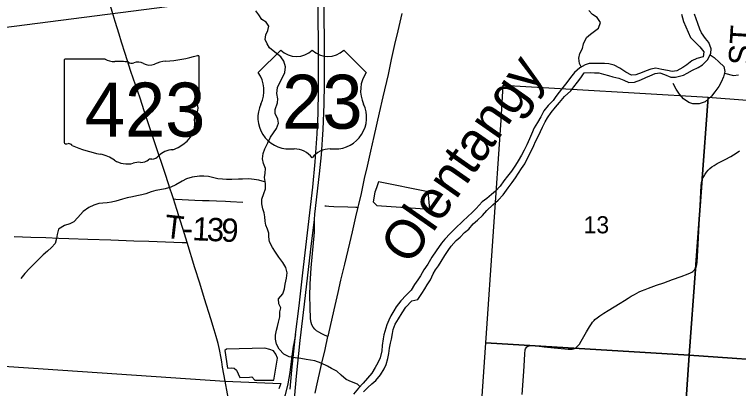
# Model space of a CAD drawing. Extents: x 1584893 to 1934202, y 663575 to 1091909.
# Drawn here: x 1804696 to 1814023, y 898063 to 902888 of the extents above; entities that cross this region are included whole.
import ezdxf

# ---------------------------------------------------------------- set-up
doc = ezdxf.new("R2010")
doc.units = 0
for name, color, linetype in [('GM_X_Corporation', 7, 'Continuous'), ('GM_X_County_Road_Text', 7, 'Continuous'), ('GM_X_Interchange_Ramps', 7, 'Continuous'), ('GM_X_Major_River', 7, 'Continuous'), ('GM_X_Major_River_Text', 7, 'Continuous'), ('GM_X_Minor_Lake', 7, 'Continuous'), ('GM_X_Minor_River', 7, 'Continuous'), ('GM_X_Section', 7, 'Continuous'), ('GM_X_Section_Text', 7, 'Continuous'), ('GM_X_State_Route', 7, 'Continuous'), ('GM_X_State_Shield', 7, 'Continuous'), ('GM_X_Township_Road', 7, 'Continuous'), ('GM_X_Township_Road_Text', 7, 'Continuous'), ('GM_X_US_Location', 7, 'Continuous'), ('GM_X_US_Route', 7, 'Continuous'), ('GM_X_US_Shield', 7, 'Continuous')]:
    doc.layers.add(name, color=color, linetype=linetype)

msp = doc.modelspace()

# ---------------------------------------------------------------- linework, layer by layer
at = {"layer": 'GM_X_Corporation'}
msp.add_lwpolyline([(1803668.3, 898412.1), (1807407.3, 898159.3), (1808126, 898128.1), (1808102.5, 898059.9)], dxfattribs=at)
at = {"layer": 'GM_X_Interchange_Ramps'}
for points in [[(1808734.7, 898733.4), (1808719.4, 898740), (1808689.4, 898753), (1808653.5, 898770.5), (1808616.3, 898790.9), (1808588.6, 898808.9), (1808563.5, 898830.2), (1808542.9, 898855.5), (1808527.9, 898884.2), (1808518.4, 898915.3), (1808511.4, 898964.2), (1808503.2, 899112.3), (1808500.5, 899260.4), (1808504.8, 899408.3), (1808519.4, 899621.7), (1808561.4, 900079.6), (1808560.6, 900147.7), (1808559.4, 900245.2)], [(1808317.9, 898761.3), (1808293.9, 898644.8), (1808285.8, 898604.8), (1808266.6, 898448.2), (1808243.1, 898270.3), (1808217.1, 898125.9), (1808184.2, 897982.8), (1808156.9, 897888.9), (1808123.3, 897797), (1808082.9, 897707.9), (1808016.2, 897577), (1807998.3, 897531.6), (1807990.2, 897500.2), (1807984.8, 897451.6), (1807985, 897386.4), (1807990.2, 897340), (1807991.6, 897328.2)]]:
    msp.add_lwpolyline(points, dxfattribs=at)
at = {"layer": 'GM_X_Major_River'}
for points in [[(1813286.7, 902892.4), (1813315.4, 902797.7), (1813344.4, 902729), (1813373.4, 902658.4), (1813406.5, 902591.7), (1813457.9, 902540.8), (1813525, 902469.7), (1813574.2, 902406.8), (1813567.2, 902342.6), (1813486.7, 902321.7), (1813422.1, 902288.5), (1813357.1, 902237.2), (1813304.5, 902203.8), (1813229.7, 902162.7), (1813169.4, 902153.5), (1813107.4, 902166.4), (1813035.4, 902177.4), (1812959.5, 902196.5), (1812893.1, 902183.4), (1812832.7, 902162.2), (1812782.2, 902138.8), (1812699.5, 902107.8), (1812645.4, 902106.5), (1812571.8, 902145.7), (1812492.3, 902197), (1812422.7, 902236), (1812350.8, 902251.1), (1812298.7, 902253.8), (1812240.6, 902254.6), (1812166.4, 902257.7), (1812100.2, 902254.5), (1812047.8, 902237.2), (1811977.1, 902202.1), (1811910, 902140.8), (1811856.9, 902073.3), (1811811.8, 902009.7), (1811758.7, 901944.2), (1811713.7, 901884.6), (1811670.8, 901829), (1811633.9, 901777.3), (1811572.8, 901714), (1811515.6, 901644.5), (1811474.4, 901566.8), (1811435.2, 901493.1), (1811390, 901425.5), (1811356.7, 901343.7), (1811331.8, 901283.8), (1811294.5, 901206.1), (1811261.4, 901138.3), (1811226.4, 901072.6), (1811183.2, 900998.9), (1811150.3, 900945.2), (1811097, 900867.7), (1811047.9, 900802.1), (1811000.8, 900740.5), (1810951.7, 900675), (1810890.6, 900609.6), (1810839.8, 900564.2), (1810778.9, 900514.8), (1810722.1, 900469.5), (1810642.6, 900386.3), (1810593.8, 900334.8), (1810536.8, 900283.4), (1810471.8, 900224.1), (1810372.1, 900129.2), (1810309, 900061.8), (1810241.7, 899990.5), (1810198.8, 899936.9), (1810127.2, 899837.6), (1810073.8, 899758), (1810020.3, 899666.5), (1809969.1, 899592.9), (1809925.9, 899517.3), (1809891, 899463.6), (1809850, 899403.9), (1809804.8, 899332.3), (1809743.7, 899266.9), (1809674.4, 899193.7)], [(1810010.3, 899399.7), (1810053.4, 899465.3), (1810090.7, 899543.1), (1810119.5, 899594.8), (1810156.4, 899646.5), (1810191.3, 899700.2), (1810238.5, 899777.8), (1810283.7, 899845.4), (1810322.6, 899901.1), (1810383.8, 899972.5), (1810438.6, 900015.9), (1810493.7, 900077.3), (1810550.5, 900120.7), (1810605.6, 900186.1), (1810662.4, 900235.5), (1810723.5, 900294.9), (1810782.6, 900360.3), (1810859.9, 900431.4), (1810927, 900494.7), (1810990.2, 900562.1), (1811055.6, 900651.5), (1811106.8, 900721), (1811149.8, 900780.6), (1811190.8, 900840.3), (1811227.8, 900900), (1811268.8, 900963.6), (1811312.3, 901053.3), (1811351.5, 901127), (1811384.6, 901196.8), (1811409.5, 901248.6), (1811440.5, 901312.4), (1811471.5, 901378.2), (1811498.5, 901436), (1811531.6, 901503.8), (1811560.4, 901555.6), (1811611.6, 901625.1), (1811666.7, 901692.6), (1811715.7, 901752.1), (1811783.1, 901829.5), (1811862.4, 901902.6), (1811901.2, 901954.3), (1811948.3, 902015.8), (1811993.2, 902071.4), (1812036.3, 902137), (1812110.5, 902138), (1812166.6, 902137.2), (1812224.7, 902134.4), (1812282.7, 902119.6), (1812348.5, 902100.6), (1812404.4, 902083.8), (1812482.4, 902066.7), (1812546.1, 902039.7), (1812609.9, 902010.7), (1812682.1, 902015.7), (1812764.8, 902046.7), (1812827.4, 902073.9), (1812881.8, 902095.2), (1812950.4, 902126.4), (1813008.7, 902133.6), (1813070.5, 902112.7), (1813150.3, 902081.5), (1813210.4, 902078.7), (1813262.7, 902092), (1813313.1, 902107.3), (1813363.5, 902130.7), (1813430.3, 902167.9), (1813503, 902205.1), (1813557.7, 902240.4), (1813628.9, 902307.7), (1813668.2, 902387.4), (1813671, 902445.6), (1813642.2, 902528.2), (1813596.8, 902579), (1813547.8, 902650), (1813524.5, 902700.4), (1813497.5, 902773.1), (1813476.3, 902833.6), (1813457.2, 902894)], [(1809193.7, 898022.3), (1809246.7, 898077.8), (1809297.5, 898125.3), (1809350.3, 898168.7), (1809409.5, 898238.1), (1809456.7, 898315.7), (1809483.7, 898375.5), (1809504.9, 898449.5), (1809519.9, 898515.5), (1809529, 898585.6), (1809541.9, 898649.7), (1809552.7, 898701.7), (1809563.8, 898771.8), (1809574.6, 898823.8), (1809601.7, 898893.6), (1809642.9, 898961.3), (1809692.1, 899038.9), (1809739.3, 899112.5), (1809814.8, 899195.7), (1809891.2, 899210.7), (1809944.5, 899290.2), (1809981.5, 899347.9), (1810010.3, 899399.7)], [(1809674.4, 899193.7), (1809615.1, 899118.2), (1809584.2, 899064.5), (1809545.2, 899002.8), (1809518.3, 898947), (1809493.3, 898883.1), (1809455.3, 898757.2), (1809446.5, 898703.2), (1809433.2, 898619), (1809428.1, 898548.9), (1809408.8, 898460.8), (1809375.7, 898393.1), (1809340.7, 898333.4), (1809297.6, 898263.7), (1809242.4, 898196.3), (1809187.3, 898132.8), (1809126.2, 898069.4), (1809064.9, 897990)]]:
    msp.add_lwpolyline(points, dxfattribs=at)
at = {"layer": 'GM_X_Minor_Lake'}
for points in [[(1810047, 900376.5), (1810024.3, 900599.6), (1809384.6, 900730.9), (1809361.4, 900652.9), (1809338.4, 900595.1), (1809316.5, 900470.9), (1809363.9, 900424.1)], [(1809363.9, 900424.1), (1810047, 900376.5)], [(1808036.9, 898170.9), (1808085.3, 898455.2), (1808062, 898507.7), (1808032.6, 898550.3), (1807986.7, 898569), (1807920.8, 898584), (1807427.3, 898570.8), (1807405, 898555), (1807441.7, 898325.8), (1807489.9, 898331.1), (1807528, 898326.6), (1807555.7, 898302.1), (1807600.4, 898207.2), (1807722.7, 898209.4), (1807754.8, 898213), (1807790.3, 898170.4)], [(1807790.3, 898170.4), (1808036.9, 898170.9)]]:
    msp.add_lwpolyline(points, dxfattribs=at)
at = {"layer": 'GM_X_Minor_River'}
for points in [[(1809147, 898090.9), (1809115, 898121.8), (1809039.2, 898148.9), (1808969.5, 898180), (1808904.1, 898235.1), (1808846.7, 898286.1), (1808781.1, 898323.1), (1808729.4, 898349.9), (1808647.8, 898391.2), (1808564, 898420.4), (1808508, 898429.3), (1808454, 898436), (1808386, 898449), (1808311.9, 898458.1), (1808236, 898473.2), (1808166.3, 898508.3), (1808105.1, 898569.3), (1808069.9, 898634), (1808056.9, 898700.5), (1808059.6, 898750.6), (1808072.6, 898814.6), (1808083.4, 898864.7), (1808098.2, 898918.6), (1808113.3, 898988.7), (1808114.3, 899050.8), (1808127.1, 899104.8), (1808099.8, 899157.4), (1808098.7, 899219.6), (1808151.9, 899285.1), (1808174.9, 899349), (1808183.8, 899411.1), (1808199, 899485.1), (1808210, 899555.2), (1808191, 899625.7), (1808151.9, 899690.5), (1808102.8, 899757.4), (1808057.7, 899824.2), (1808020.4, 899883), (1807979.4, 899953.8), (1807972.3, 900018.1), (1807971.1, 900068.3), (1807955.8, 900120.7), (1807934.5, 900171.1), (1807925.2, 900221.4), (1807922.1, 900279.7), (1807912.8, 900330), (1807897.6, 900382.3), (1807884.5, 900446.8), (1807883.4, 900507), (1807908.5, 900578.9), (1807931.5, 900640.8), (1807928.5, 900707), (1807917.7, 900787.4), (1807924.5, 900839.5), (1807931.4, 900903.7), (1807904.3, 900968.2), (1807889.1, 901024.7), (1807900.2, 901094.7), (1807923.2, 901154.6), (1807960.4, 901234.4), (1807993.6, 901304.1), (1808032.5, 901359.8), (1808071.5, 901419.4), (1808098.6, 901487.3), (1808087.3, 901537.6), (1808054.3, 901610.3), (1808055.1, 901664.5), (1808084.4, 901748.4), (1808087.2, 901800.5), (1808076.2, 901868.9), (1808085.4, 901945), (1808114.4, 902008.8), (1808145.4, 902068.6), (1808178.5, 902140.4), (1808187.6, 902212.5), (1808164.7, 902287.1), (1808125.4, 902343.8), (1808052.1, 902401), (1807982.8, 902458.2), (1807949.5, 902510.8), (1807926.2, 902565.3), (1807935.2, 902627.4), (1807962, 902681.2), (1807970.9, 902735.3), (1807937.6, 902789.9), (1807882, 902822.8), (1807842.8, 902883.5), (1807803.4, 902934.3)], [(1811995.1, 902211), (1811975.9, 902256.3), (1811964.9, 902324.7), (1811979.8, 902384.6), (1812012.9, 902450.4), (1812027.8, 902510.4), (1812065.2, 902592.2), (1812115.9, 902635.6), (1812166.6, 902673.1), (1812221.3, 902712.4), (1812246.5, 902786.3), (1812201.3, 902847.2), (1812143.8, 902888.1), (1812096.4, 902940.9)], [(1813658.3, 902367.4), (1813709.4, 902332.7), (1813774.7, 902271.5), (1813834, 902218.5), (1813845.1, 902152.2), (1813830, 902084.1), (1813800.9, 902016.3), (1813768, 901960.6), (1813718.9, 901891), (1813673.9, 901833.4), (1813592.6, 901762.3), (1813514.1, 901737.3), (1813435.8, 901734.4), (1813382, 901753.2), (1813314.5, 901802.3), (1813263.3, 901861.2), (1813220.1, 901926), (1813181.1, 901996.8)], [(1813840.4, 902131.1), (1813956.6, 902102.4), (1814024.9, 902109.5)], [(1807924.8, 900734.6), (1807914.8, 900731.3), (1807844.9, 900750.3), (1807782.9, 900761.2), (1807716.9, 900768.2), (1807634.6, 900765.3), (1807582.4, 900762), (1807496.2, 900759.2), (1807426, 900760.2), (1807375.9, 900764.9), (1807317.9, 900769.8), (1807263.9, 900780.5), (1807194, 900797.6), (1807135.9, 900804.4), (1807081.7, 900803.2), (1806983.3, 900788.5), (1806912.8, 900769.4), (1806856.2, 900740.1), (1806773.3, 900691.1), (1806710.6, 900659.8), (1806638.1, 900638.8), (1806569.8, 900625.7), (1806517.5, 900618.4), (1806459.1, 900599.2), (1806386.5, 900574.1), (1806336.2, 900562.8), (1806271.9, 900549.6), (1806217.5, 900536.3), (1806149.2, 900523.2), (1806088.8, 900508), (1806002.1, 900479.1), (1805947.8, 900467.9), (1805889.5, 900456.6), (1805833.3, 900453.4), (1805783.1, 900448.1), (1805716.6, 900427), (1805652, 900397.8), (1805583.1, 900346.6), (1805513.7, 900269.3), (1805458.8, 900215.8), (1805408.2, 900186.5), (1805339.7, 900165.3), (1805262.8, 900118.3), (1805247.8, 900050.2), (1805239, 900000.2), (1805220, 899936.2), (1805175, 899880.7), (1805122.2, 899833.3), (1805067.3, 899785.9), (1805008.4, 899732.5), (1804947.3, 899667.2), (1804890.3, 899611.8), (1804829.2, 899548.4), (1804780.1, 899482.9)]]:
    msp.add_lwpolyline(points, dxfattribs=at)
at = {"layer": 'GM_X_Section'}
for points in [[(1808771.7, 905367.5), (1808765.7, 905039.5), (1808764.7, 903261.2), (1808466.3, 903222.7), (1803483.6, 902579.7), (1803482.3, 905286.1)], [(1813632.6, 901820.9), (1813386, 898491.9), (1810768.6, 898652.1), (1810964.3, 901523.4), (1810993.1, 901977.3)], [(1813682.5, 901815.9), (1816281, 901618.9), (1819013.3, 901451.7), (1818796.6, 898114.4), (1813386, 898491.9), (1813632.6, 901820.9)], [(1813386, 898491.9), (1813022.7, 893121.3), (1810407.3, 893289.5), (1810489.6, 894489.9), (1810726.9, 898030.6), (1810768.6, 898652.1)], [(1818796.6, 898114.4), (1818447.1, 892717.6), (1813022.7, 893121.3), (1813386, 898491.9)]]:
    msp.add_lwpolyline(points, close=True, dxfattribs=at)
at = {"layer": 'GM_X_State_Route'}
for points in [[(1806601.5, 900940.3), (1806546.9, 901105.3), (1806454.8, 901385.8), (1806367.6, 901645.9), (1806313.7, 901807.3), (1806196.7, 902152.5), (1806120.6, 902385.5), (1806076, 902531.1), (1806046.4, 902632.8), (1805994.3, 902796.6), (1805956.2, 902926.5), (1805907.1, 903089.9)], [(1808569.1, 898005.7), (1808588.6, 898085.6), (1808652.7, 898373.9), (1808696.5, 898565.9), (1808734.7, 898733.4), (1808740.3, 898757.8), (1808814.5, 899077.4), (1808865.2, 899301.8), (1808902, 899460.9), (1808951.4, 899668.8), (1809015.1, 899939.8), (1809049.1, 900084.6), (1809092.8, 900276.3), (1809122.1, 900402.7), (1809130.7, 900438.7), (1809164.3, 900579.5), (1809207.2, 900771.6), (1809243.8, 900931.5), (1809288.5, 901123), (1809330.8, 901316.1), (1809398.8, 901619.3), (1809446.3, 901827.8), (1809512.4, 902115.7), (1809554.5, 902308.1), (1809597.8, 902500.2), (1809637.3, 902676.4), (1809688.8, 902900.4)], [(1806716.9, 900589.3), (1806706.3, 900622.3), (1806639.7, 900824.9), (1806601.5, 900940.3)], [(1807366, 898408.5), (1807357.6, 898456.4), (1807338.1, 898566), (1807321.4, 898645.7), (1807295.4, 898735.8), (1807269.6, 898822.1), (1807225.5, 898962.9), (1807144, 899221.1), (1807081.8, 899424.3), (1807021.1, 899620.9), (1806920.1, 899947.2), (1806885.3, 900059.7), (1806786.5, 900372.5), (1806742.7, 900508.9), (1806716.9, 900589.3)], [(1807411.5, 898159.5), (1807378, 898339.5), (1807366, 898408.5)], [(1807556.9, 897369.3), (1807539.7, 897461.6), (1807470, 897833.8), (1807411.5, 898159.5)]]:
    msp.add_lwpolyline(points, dxfattribs=at)
at = {"layer": 'GM_X_State_Shield'}
for p, q in [((1805336, 902295.6), (1805336, 901238.9)), ((1805862.8, 902313.8), (1805353.2, 902313.8)), ((1807076.2, 901787.2), (1807076.2, 902339.9)), ((1807076.1, 901787.3), (1807076.2, 901787.2))]:
    msp.add_line(p, q, dxfattribs=at)
for centre, major_axis, start_param, end_param in [((1805356, 902297.8), (20.2, 0), 1.712693, 3.28349), ((1805984.2, 902436.4), (195.5, 0), 4.042523, 4.731795), ((1806049, 901720.6), (702, 0), 1.404758, 1.657858), ((1806208.4, 902303.3), (56.4, 0), 3.836095, 5.185415), ((1806291.2, 902181.2), (117.3, 0), 0.950623, 2.079405), ((1806691.7, 901991), (371.3, 0), 1.699011, 2.107814), ((1806456.4, 903754.3), (1845.5, 0), 4.814394, 5.042369), ((1807056.9, 902342.2), (19.4, 0), 6.141152, 7.989035), ((1806442.6, 902348.7), (141.1, 0), 4.081561, 5.145723), ((1807071.8, 901746.6), (30, 0), 1.883978, 3.671073), ((1806881, 901676.8), (180, 0), 5.934695, 6.695948), ((1807055.6, 901785.1), (20.7, 0), 5.05454, 6.418171), ((1807145.6, 901555.9), (130.9, 0), 2.387724, 3.262537), ((1806559.7, 901485.6), (461.6, 0), 5.101752, 6.440018), ((1805356.2, 901236.6), (20.3, 0), 3.00124, 4.508301), ((1805359.2, 901344.7), (155.2, 0), 4.665946, 4.897461), ((1805391, 901178), (56, 0), 0.519207, 1.627899), ((1806097.6, 902127.3), (1332.7, 0), 4.195997, 4.488961), ((1805700.3, 900764.2), (417, 0), 0.823519, 1.323587), ((1806434.1, 901136.5), (149.1, 0), 4.937069, 5.64225), ((1806754.4, 900942.3), (252.8, 0), 1.647645, 2.488434), ((1806151.2, 901172.7), (264.6, 0), 4.026481, 4.996735), ((1806304.1, 900807.4), (217.4, 0), 1.495662, 1.94098), ((1806323.5, 901093.6), (141, 0), 4.691044, 5.507374), ((1806451, 900991.3), (39.7, 0), 1.147584, 2.315152)]:
    msp.add_ellipse(centre, major_axis=major_axis, ratio=0.8, start_param=start_param, end_param=end_param, dxfattribs=at)
at = {"layer": 'GM_X_Township_Road'}
for points in [[(1811237, 897988.3), (1811256.7, 898283), (1811266.7, 898430.3), (1811271, 898512.2), (1811275.8, 898560.5), (1811280.1, 898575.3), (1811287.6, 898588.5), (1811298.1, 898599.6), (1811310.6, 898608.5), (1811324.7, 898614.5), (1811339.8, 898617.9), (1811355.5, 898618.8), (1811371.6, 898618.1), (1811454.8, 898609.4), (1811518.3, 898602.8), (1811649.1, 898589.4), (1811828.9, 898571.2), (1811862.2, 898570), (1811879.1, 898571.2), (1811895.9, 898574.6), (1811912, 898581), (1811926.6, 898589.9), (1811939.7, 898600.5), (1811951.7, 898612.2), (1811973.2, 898637.6), (1811994.1, 898673.2), (1812065.8, 898795.2), (1812104.6, 898858.8), (1812128.3, 898897.7), (1812142.6, 898918.5), (1812161.5, 898940.9), (1812173.5, 898952.4), (1812203, 898976.7), (1812238.6, 899002.8), (1812287.2, 899035.8), (1812343.6, 899071.4), (1812419.3, 899117.6), (1812497.2, 899165.2), (1812553.3, 899199.2), (1812602.9, 899229.3), (1812640.8, 899252.8), (1812681.3, 899275.6), (1812713.4, 899293.7), (1812744.6, 899310.6), (1812774, 899324.3), (1812819.3, 899342.8), (1812865.5, 899359.1), (1812968.5, 899395.7), (1813061.6, 899428.8), (1813174.7, 899469), (1813282.4, 899508.8), (1813374.3, 899544.6), (1813404.9, 899557.7), (1813419.7, 899565.7), (1813433.8, 899574.9), (1813446.8, 899585.6), (1813458.4, 899598), (1813468.3, 899611.8), (1813476.5, 899626.6), (1813482.8, 899642.5), (1813487.2, 899658.8), (1813491.5, 899691.9), (1813502.9, 899921.7), (1813517.7, 900183.9), (1813525.3, 900331.4), (1813534.4, 900511), (1813543.9, 900679.5), (1813547.4, 900722.9), (1813555.2, 900755.9), (1813560.4, 900771.5), (1813567.6, 900786), (1813574.8, 900800.3), (1813592.3, 900827.5), (1813611.4, 900853.8), (1813632.3, 900878.5), (1813655.4, 900901.1), (1813680.6, 900921.5), (1813707.4, 900939.7), (1813749.5, 900964.7), (1813850.9, 901018.7), (1813923, 901058.2), (1813993.3, 901101.2), (1814033.8, 901129.8)], [(1806742.7, 900508.9), (1806776.5, 900507.1), (1806857.6, 900503), (1807020.9, 900495.2), (1807119, 900490.9), (1807202.3, 900487.4), (1807300.4, 900484), (1807414.6, 900478.4), (1807480.1, 900476.2), (1807639, 900469.3)], [(1808695.4, 900420.8), (1808711.7, 900419.8), (1808744.3, 900417.2), (1808809.9, 900413), (1808991.1, 900407), (1809094.7, 900403.6), (1809122.1, 900402.7)], [(1804692.6, 900025.3), (1804905.4, 900016.7), (1805102, 900009.8), (1805265.9, 900004.5), (1805396.9, 899999.9), (1805642.6, 899990.9), (1805937.4, 899980.4), (1806232.4, 899970.2), (1806428.9, 899962.9), (1806854.9, 899948.9), (1806887.7, 899948.1), (1806920.1, 899947.2)]]:
    msp.add_lwpolyline(points, dxfattribs=at)
at = {"layer": 'GM_X_US_Route'}
for points in [[(1808514.8, 899862.9), (1808559.4, 900245.2), (1808566.1, 900310.8), (1808627.4, 900832.2), (1808650.2, 901077.1), (1808671.7, 901404.4), (1808685.6, 901732.1), (1808690, 901994.4), (1808686.7, 903421.7), (1808682.7, 904537.4), (1808682.4, 904765.9)], [(1808248.5, 898053.9), (1808269.5, 898299), (1808311.4, 898706.8), (1808317.9, 898761.3), (1808362.2, 899130.3), (1808411, 899554.1), (1808539.5, 900662.3), (1808570.3, 900989.1), (1808596.2, 901349.2), (1808608.3, 901611.6), (1808612.8, 901907), (1808609.7, 903465.6)], [(1808478.7, 894878.3), (1808476.8, 894905), (1808461.5, 895051.6), (1808387.2, 895571.3), (1808352.9, 895864.7), (1808351.7, 895878.4), (1808323.1, 896175.1), (1808303.3, 896469.9), (1808289.4, 896781.3), (1808284.4, 897093.1), (1808285.7, 897405), (1808288.3, 897497), (1808288.6, 897510.3), (1808293.8, 897683.9), (1808309.2, 897978.9), (1808328.6, 898224.3), (1808376.2, 898681.2), (1808431.9, 899153.7), (1808514.8, 899862.9)]]:
    msp.add_lwpolyline(points, dxfattribs=at)
at = {"layer": 'GM_X_US_Shield'}
for p, q in [((1808125.7, 902429.9), (1807835.6, 902139.8)), ((1809227.8, 902139.8), (1808937.8, 902429.9)), ((1808241.7, 901153.7), (1808299.7, 901153.7)), ((1808763.8, 901153.7), (1808821.8, 901153.7))]:
    msp.add_line(p, q, dxfattribs=at)
for centre, radius, start, end in [((1808328.7, 902637), 290, 225.573, 314.427), ((1808734.8, 902637), 290, 225.573, 314.427), ((1807503, 901906.9), 406.1, 334.54712, 35.00093), ((1809560.5, 901906.9), 406.1, 144.99907, 205.45288), ((1808237.2, 901559.7), 406.1, 154.83192, 270.63826), ((1808826.3, 901559.7), 406.1, 269.36174, 25.16808), ((1808299.7, 900863.7), 290, 36.8699, 90), ((1808763.8, 900863.7), 290, 90, 143.1301)]:
    msp.add_arc(centre, radius, start, end, dxfattribs=at)

# ---------------------------------------------------------------- texts
at = {"layer": 'GM_X_County_Road_Text'}
msp.add_text('ST', height=300, rotation=86.46009, dxfattribs=at).set_placement((1814190.8, 902225.5))
at = {"layer": 'GM_X_Major_River_Text'}
msp.add_text('Olentangy', height=500.09, rotation=55.01549, dxfattribs=at).set_placement((1809786.3, 899637.3))
at = {"layer": 'GM_X_Section_Text'}
msp.add_text('13', height=221, rotation=0.00001, dxfattribs=at).set_placement((1812027.4, 900065.5))
at = {"layer": 'GM_X_State_Shield'}
msp.add_text('423', height=696.1, dxfattribs=at).set_placement((1805601.8, 901313.5))
at = {"layer": 'GM_X_Township_Road_Text'}
for s, rotation, p in [('T', 353.4698, (1806614.9, 900010.8)), ('1', 357.38844, (1806983.2, 899977)), ('3', 357.57311, (1807168.9, 899968.5)), ('9', 357.61885, (1807353.8, 899960.7)), ('-', 356.97242, (1806857.8, 899983.6))]:
    msp.add_text(s, height=300, rotation=rotation, dxfattribs=at).set_placement(p)
at = {"layer": 'GM_X_US_Location'}
for s in ['/', '0']:
    msp.add_text(s, height=1, dxfattribs=at).set_placement((1808412.5, 898953.7))
msp.add_text('23', height=1, rotation=0.00001, dxfattribs=at).set_placement((1808206, 898746.7))
at = {"layer": 'GM_X_US_Shield'}
msp.add_text('23', height=696.1, dxfattribs=at).set_placement((1808144.3, 901414.7))

doc.saveas('drawing.dxf')
